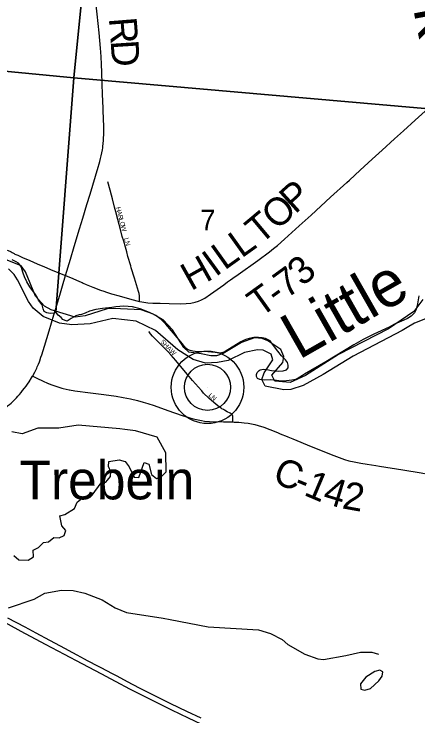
# Model space of a CAD drawing. Extents: x 1410790 to 1770854, y 448063 to 770588.
# Drawn here: x 1548544 to 1552911, y 621077 to 628670 of the extents above; entities that cross this region are included whole.
import ezdxf

# ---------------------------------------------------------------- set-up
doc = ezdxf.new("R2010")
doc.units = 0
for name, color, linetype in [('GM_X_County_Road', 7, 'Continuous'), ('GM_X_County_Road_Text', 7, 'Continuous'), ('GM_X_Major_River', 7, 'Continuous'), ('GM_X_Major_River_Text', 7, 'Continuous'), ('GM_X_Minor_Lake', 7, 'Continuous'), ('GM_X_Minor_River', 7, 'Continuous'), ('GM_X_Minor_River_Text', 7, 'Continuous'), ('GM_X_Section', 7, 'Continuous'), ('GM_X_Section_Text', 7, 'Continuous'), ('GM_X_Township_Road', 7, 'Continuous'), ('GM_X_Township_Road_Text', 7, 'Continuous'), ('GM_X_Township_Subdivision', 7, 'Continuous'), ('GM_X_Township_Subdivision_Text', 7, 'Continuous'), ('GM_X_Unincorporated', 7, 'Continuous'), ('GM_X_Unincorporated_Location', 7, 'Continuous'), ('GM_X_Unincorporated_Text', 7, 'Continuous'), ('GM_X_US_Route', 7, 'Continuous')]:
    doc.layers.add(name, color=color, linetype=linetype)

msp = doc.modelspace()

# ---------------------------------------------------------------- linework, layer by layer
at = {"layer": 'GM_X_County_Road'}
for points in [[(1549508.2, 627624), (1549507.3, 627650.8), (1549502.1, 627802.3), (1549497.6, 627911.9), (1549492.5, 628036.7), (1549488.6, 628126.5), (1549485.2, 628206.8), (1549482.1, 628256.7), (1549479.3, 628301.4), (1549464.4, 628464.7), (1549444, 628667), (1549425.8, 628836.6), (1549397.5, 629101.8), (1549381.4, 629253.7), (1549372.3, 629343.1), (1549344.5, 629616.5), (1549338.5, 629679.9), (1549335, 629723.3), (1549332.8, 629751.5), (1549330.7, 629782.3), (1549328.9, 629824.9), (1549327.6, 629859.6)], [(1549513, 627365.4), (1549514.1, 627400.6), (1549513.8, 627453), (1549508.2, 627624)], [(1549331.9, 626608.2), (1549366.8, 626722.6), (1549453.5, 627013.7), (1549463, 627048), (1549470.4, 627074.4), (1549478.7, 627106.6), (1549485.2, 627135.1), (1549492.5, 627168.6), (1549499.1, 627199.9), (1549503, 627222), (1549505.3, 627237.6), (1549508.5, 627269.9), (1549510.8, 627302.7), (1549511.9, 627328.7), (1549513, 627365.4)], [(1549100.3, 625839.9), (1549154.4, 626018.5), (1549194.8, 626154.3), (1549252.5, 626345.3), (1549287.7, 626463.3), (1549331.9, 626608.2)], [(1548470.7, 626114.6), (1548498.1, 626103.4), (1548511.1, 626097.4), (1548522.8, 626091.3), (1548536.7, 626083.1), (1548545.4, 626077.8), (1548553.6, 626073.5), (1548583.2, 626060), (1548636.1, 626037.5), (1548712.9, 626004.9), (1548795.4, 625969.3), (1548874.4, 625935), (1548963.3, 625896.8), (1549100.3, 625839.9)], [(1548745.6, 624754.3), (1548753.9, 624769), (1548768.1, 624795.2), (1548782.4, 624824), (1548789.8, 624839.1), (1548795.4, 624852.5), (1548808.4, 624883.4), (1548817.5, 624907.7), (1548824.9, 624927.9), (1548826.2, 624931.5), (1548835.3, 624958.9), (1548843.6, 624983.6), (1548873.1, 625078.7), (1548922.6, 625243.2), (1548975.1, 625416.3), (1548995.9, 625485.4), (1549045.4, 625655), (1549067.1, 625728), (1549100.3, 625839.9)], [(1548413.2, 624383.4), (1548450.8, 624412), (1548474.7, 624431.1), (1548493.3, 624447.1), (1548511.1, 624462.3), (1548526.3, 624475.8), (1548538.4, 624487.1), (1548551, 624499.7), (1548568.8, 624518.3), (1548585.7, 624537), (1548601.4, 624555.2), (1548619.2, 624575.6), (1548637, 624597.3), (1548656.1, 624621.7), (1548674.3, 624645.1), (1548689.5, 624666.8), (1548705.7, 624691.3), (1548734, 624735.3), (1548744.2, 624751.8), (1548745.6, 624754.3)], [(1548745.6, 624754.3), (1548795.8, 624729.1), (1548852.8, 624700.4), (1548912.7, 624673.1), (1548916.5, 624671.6)], [(1548916.5, 624671.6), (1548942.4, 624661.4), (1548973, 624650.2), (1549017.5, 624635.7), (1549060.8, 624623.7), (1549075.7, 624619.6), (1549107.6, 624611.4), (1549138.6, 624605)], [(1549138.6, 624605), (1549141.8, 624604.3), (1549201, 624593.9), (1549369.9, 624571.7), (1549513.3, 624554.2), (1549649.8, 624534.9), (1549724.3, 624522.5), (1549801.6, 624506.6), (1549878.3, 624488.2), (1549941.8, 624471.1), (1549989, 624456.7), (1550057.4, 624433.7), (1550206.5, 624382.7), (1550360.8, 624327.4), (1550432.4, 624304.3), (1550479.6, 624291.1), (1550533.6, 624278.6), (1550572.2, 624271.8), (1550604.4, 624267.4), (1550656.4, 624263.3), (1550807.7, 624258.5), (1550909.7, 624257.1)], [(1550909.7, 624257.1), (1550925.7, 624256.8), (1550974.6, 624254.6), (1551033.6, 624249.3), (1551076.1, 624243.7), (1551111.8, 624237.2), (1551147.2, 624229.2), (1551185.3, 624218.6), (1551244.9, 624199.4), (1551309.5, 624175.1), (1551391.9, 624142.6), (1551421.9, 624129.8), (1551496.8, 624100.4)], [(1551496.8, 624100.4), (1551503, 624098), (1551559.9, 624074.5), (1551755.9, 623993.3), (1552002, 623893.7), (1552060.1, 623871.3), (1552115.8, 623852.3), (1552162.7, 623838.5), (1552223, 623824.3), (1552294.1, 623812.9), (1552362.2, 623802.1), (1552456, 623786.2), (1552494.7, 623779.6), (1552747.4, 623739.8), (1552944.7, 623705.8), (1553096.5, 623679.4), (1553252.7, 623654.1)]]:
    msp.add_lwpolyline(points, dxfattribs=at)
at = {"layer": 'GM_X_Major_River'}
for points in [[(1552964.5, 625583.2), (1552867.5, 625453), (1552593.1, 625264.6), (1552050.4, 624985.8), (1551697.1, 624760.9), (1551529.2, 624684.4), (1551363.3, 624698), (1551330.8, 624764.8), (1551451.9, 624900.5), (1551459.3, 624966.4), (1551426.9, 625041.3), (1551288.9, 625136.4), (1551225.4, 625161.8), (1551143.4, 625165.6), (1551004.1, 625116.5), (1550805.3, 624998.6), (1550734.7, 624974.1), (1550670.6, 624971.4), (1550567, 624993.7), (1550435.2, 625012.6), (1550380.3, 625061.8), (1550256.3, 625252.9), (1550156.6, 625363.2), (1550041.9, 625427.8), (1549918.7, 625468.5), (1549694.7, 625481.4), (1549626.7, 625482.8), (1549550.5, 625480.5), (1549312.6, 625405.4), (1549204.2, 625391.8), (1548943.6, 625469.5), (1548874.4, 625509), (1548774.7, 625617.4), (1548666.4, 625882.2), (1548621.7, 625945.3), (1548435.2, 626023.4)], [(1551260.1, 624646.1), (1551223.6, 624715), (1551249.2, 624788.6), (1551342.4, 624928.9), (1551325.7, 624991.4), (1551236.6, 625035.4), (1551176.6, 625036.7), (1551035.8, 625009.7), (1550859.7, 624923.3), (1550745.1, 624899.7), (1550614.8, 624894.5), (1550481.5, 624933.4), (1550315.6, 625037.2), (1550074, 625246.8), (1549865.9, 625347.4), (1549610.3, 625377), (1549368.8, 625318.1), (1549170.3, 625308.3), (1549036.6, 625327.2), (1548860, 625399.2), (1548749.8, 625487.7), (1548699.3, 625558.9), (1548582.3, 625793.8), (1548545.5, 625850.7), (1548482.8, 625912.2)], [(1552993.9, 625372.2), (1552872.8, 625326.7), (1552793.6, 625278.3), (1552738.9, 625245.4), (1552212.2, 624968.2), (1551887.5, 624770.8), (1551670.7, 624651.3), (1551537.6, 624610.1), (1551459.4, 624603.8), (1551260.1, 624646.1)]]:
    msp.add_lwpolyline(points, dxfattribs=at)
at = {"layer": 'GM_X_Minor_Lake'}
for points in [[(1548542.8, 622813.3), (1548596.1, 622766.2), (1548698.2, 622760.5), (1548755, 622799.6), (1548752.2, 622869.9), (1548808.8, 622899), (1548861.9, 622952.3), (1548918.2, 622961.3), (1548975.1, 623006.5), (1549033.2, 623003.5), (1549085.8, 623030.7), (1549104.7, 623082.5), (1549061.4, 623133.4), (1549039.2, 623242.1), (1549093.6, 623255.2), (1549196.9, 623319.6), (1549228.2, 623389.3), (1549279.1, 623432.5), (1549387.9, 623466.8), (1549484.4, 623597.5), (1549536.6, 623606.6), (1549585.8, 623666), (1549588.7, 623718.1), (1549565.6, 623776.6), (1549570.5, 623828.7), (1549681.1, 623846.9), (1549744.9, 623829.7), (1549790.1, 623772.8), (1549842.3, 623659.6), (1549894.3, 623656.7), (1549949.2, 623818.2), (1550003.1, 623801.2), (1550031.2, 623690.4), (1550084.6, 623647.4), (1550135, 623662.5), (1550188.1, 623717.8), (1550185.6, 623924.4), (1550092.2, 624092.5), (1549858.9, 624162.7), (1549740.8, 624176.8), (1549686.8, 624181.7), (1549238.4, 624221.5), (1549029.4, 624191), (1548923.1, 624190.8), (1548800.8, 624188.9), (1548633.4, 624127.6), (1548521.5, 624149.6)], [(1552525.4, 621507.1), (1552530.4, 621553.2), (1552498.7, 621571.9), (1552444.3, 621559), (1552348.9, 621496.7), (1552289.3, 621423.7), (1552294.1, 621365.5), (1552338, 621354.5), (1552396.5, 621373.4)], [(1552396.5, 621373.4), (1552488.4, 621456.9), (1552525.4, 621507.1)]]:
    msp.add_lwpolyline(points, dxfattribs=at)
at = {"layer": 'GM_X_Minor_River'}
msp.add_lwpolyline([(1548482.9, 622246.6), (1548761.2, 622342.1), (1548878.6, 622404.3), (1549057.6, 622439.3), (1549183.8, 622433.2), (1549307.6, 622407), (1549496.8, 622333.5), (1549635.7, 622246.9), (1549759.1, 622196.6), (1550157, 622133.6), (1550233, 622120.2), (1550644.6, 622040.9), (1551187.3, 622009.5), (1551317, 621969.2), (1551444.2, 621904.8), (1551503.4, 621849.6), (1551688, 621744.1), (1551827.5, 621695.5), (1551891.5, 621688.4), (1552132.9, 621732.4), (1552291.8, 621767.8), (1552412.1, 621765.7), (1552483.9, 621746.4)], dxfattribs=at)
at = {"layer": 'GM_X_Section'}
for points in [[(1544399.7, 633789.9), (1549719.6, 633308.3), (1549189.3, 627980.4), (1543911.7, 628488)], [(1549719.6, 633308.3), (1555022.2, 632826.4), (1554631.8, 628627.9), (1554620.8, 627934.3), (1554618.6, 627918.3), (1554618, 627882.4), (1554617.3, 627836.4), (1554614.8, 627806.4), (1554624.4, 627780.3), (1554668.6, 627671.6), (1554687.9, 627625.3), (1554689.4, 627591.3), (1554684.9, 627563.4), (1554674.5, 627535.6), (1554652.2, 627519.9), (1554620, 627502.5), (1554585.9, 627497), (1554498, 627498.4), (1554418, 627499.6), (1554372, 627500.4), (1554330.2, 627507), (1554298.4, 627519.5), (1554266.6, 627536), (1549189.3, 627980.4)]]:
    msp.add_lwpolyline(points, close=True, dxfattribs=at)
for points in [[(1543911.7, 628488), (1549189.3, 627980.4), (1548997.2, 625446.3), (1548975, 625434.6), (1548940.9, 625431.2), (1548917, 625433.5), (1548897.1, 625437.9), (1548869.3, 625450.3), (1548859.7, 625480.4), (1548846.4, 625522.6), (1548807.3, 625575.2), (1548795.7, 625605.4), (1548774.3, 625637.7), (1548713.6, 625718.7), (1548680.5, 625773.2), (1548655.3, 625825.6), (1548641.9, 625865.8), (1548628.7, 625914), (1548625, 625932), (1548611.3, 625954.2), (1548591.7, 625974.5), (1548566, 625990.9), (1548522.2, 626009.6)], [(1552920.6, 625620), (1552905.3, 625534.3), (1552890.3, 625472.5), (1552873.8, 625438.8), (1552838.5, 625402.9), (1552796.8, 625376), (1552758.5, 625356.6), (1552655.9, 625314.3), (1552599.4, 625283.2), (1552434.2, 625205.8), (1552317.4, 625149.7), (1552216.5, 625093.3), (1551913.7, 624908.2), (1551685.6, 624773.8), (1551663.4, 624760.2), (1551617, 624730.9), (1551588.8, 624717.4), (1551548.6, 624708), (1551488.6, 624703), (1551436.6, 624699.8), (1551380.6, 624704.7), (1551312.8, 624711.8), (1551256.8, 624710.7), (1551200.9, 624717.6), (1551175.1, 624727.9), (1551165.4, 624750.1), (1551163.8, 624772.1), (1551174.1, 624792), (1551194.4, 624813.6), (1551206.5, 624819.4), (1551240.6, 624826.9), (1551276.6, 624824.3), (1551328.4, 624815.5), (1551402.3, 624808.3), (1551452.3, 624809.5), (1551490.4, 624820.9), (1551506.8, 624842.7), (1551509.3, 624872.6), (1551499.7, 624898.8), (1551480.2, 624931), (1551434.9, 624973.8), (1551397.7, 625022.3), (1551338.9, 625097.2), (1551313.5, 625133.6), (1551263.9, 625158.4), (1551226, 625169), (1551186.1, 625171.6), (1551136.1, 625170.4), (1551088, 625161.2), (1551049.8, 625147.8), (1551023.6, 625138.2), (1550995.4, 625124.7), (1550920.7, 625077.9), (1550856.1, 625036.9), (1550815.7, 625013.6), (1550787.6, 625006), (1550759.5, 625002.4), (1550719.6, 625007.1), (1550597.9, 625019), (1550525.9, 625016.2), (1550476, 625023), (1550448.1, 625029.4), (1550420.3, 625039.8), (1550400.5, 625056.1), (1550347.6, 625123), (1550269.1, 625216.2), (1550184.7, 625313.5), (1550133.5, 625366.3), (1550076.2, 625407.2), (1550008.8, 625442.2), (1549907.4, 625479.8), (1549823.8, 625501.1), (1549731.9, 625508.6), (1549643.9, 625504), (1549601.8, 625496.6), (1549499.6, 625486.3), (1549429.5, 625473.4), (1549361.2, 625456.5), (1549312.9, 625435.3), (1549272.6, 625419.9), (1549246.6, 625416.3), (1549210.4, 625404.9), (1549162, 625377.7), (1549117.6, 625348.4), (1549095.7, 625354.7), (1549071.9, 625367.1), (1549052.2, 625385.4), (1549022.7, 625413.9), (1548997.2, 625446.3), (1549189.3, 627980.4), (1554266.6, 627536)]]:
    msp.add_lwpolyline(points, dxfattribs=at)
at = {"layer": 'GM_X_Township_Road'}
for points in [[(1549901.8, 625560.8), (1549925.2, 625555.3), (1549967.4, 625548.6), (1549989.8, 625546.2), (1550043.5, 625543.7), (1550124.6, 625541.9), (1550220.8, 625538.9), (1550345.6, 625535.2), (1550404.9, 625537.9), (1550454.2, 625543.6), (1550502.7, 625553.9), (1550537.6, 625564.6), (1550571.4, 625578.6), (1550606.3, 625597.8), (1550666.6, 625638), (1550810.7, 625741.1), (1550853.6, 625771.3), (1550885.8, 625793.8), (1550909.7, 625811.1), (1550968.6, 625852.8), (1551179.1, 626004), (1551306.7, 626096.6), (1551350.7, 626131.9), (1551393.2, 626167.4), (1551468.3, 626235.8), (1551626.7, 626378.5), (1551755.2, 626495.6), (1551966.4, 626687.5), (1552141.4, 626846.1), (1552170.5, 626872.7), (1552286.4, 626979.3), (1552417.2, 627098.8), (1552522.7, 627197.2), (1552655.9, 627318.7), (1552754.2, 627405.4), (1552879.9, 627520.3), (1553092.2, 627713.3)], [(1549100.3, 625839.9), (1549178.9, 625809.7), (1549250.7, 625777.8), (1549280.5, 625764.3), (1549292.3, 625758.8), (1549325, 625743.9), (1549394.7, 625715.7), (1549480.2, 625682.4), (1549514.4, 625670.6), (1549542.6, 625661.6), (1549599.2, 625644.6), (1549681.2, 625621), (1549766.2, 625596.2), (1549832.6, 625577.9), (1549870.8, 625568.2), (1549901.8, 625560.8)]]:
    msp.add_lwpolyline(points, dxfattribs=at)
at = {"layer": 'GM_X_Township_Subdivision'}
for points in [[(1549901.8, 625560.8), (1549901.8, 625581.2), (1549901.8, 625604.1), (1549900, 625622.5), (1549895.9, 625645.9), (1549890.8, 625667.7), (1549868.5, 625740), (1549845.2, 625813), (1549811.4, 625925.1), (1549805.2, 625946.6), (1549775.9, 626046.9), (1549761.9, 626097.5), (1549747.7, 626148.1), (1549729.7, 626211.2), (1549714.8, 626265), (1549698.5, 626325.2), (1549666.3, 626445.7), (1549644, 626531.4), (1549630.5, 626582.1), (1549606.8, 626670.9), (1549596.1, 626712.2), (1549582.1, 626766.2), (1549559.6, 626854.5)], [(1550572.7, 624592.3), (1550569.4, 624595.8), (1550473, 624707.5), (1550436.7, 624749.8), (1550380.2, 624817.9), (1550292.1, 624923.8), (1550243.7, 624981.4), (1550208.1, 625019.5), (1550070.1, 625155), (1550040.5, 625186), (1550019.1, 625211.3), (1550005.9, 625230.6), (1550002.5, 625236.5)], [(1550909.7, 624257.1), (1550909.7, 624286.7), (1550909.7, 624313.2), (1550909.2, 624321.5), (1550907.1, 624329.7), (1550901.4, 624337.1), (1550892.7, 624344.1), (1550880.9, 624351.4), (1550849.2, 624367.8), (1550820.1, 624383.5), (1550808.9, 624390.3), (1550791.4, 624400.4), (1550786.3, 624404.3), (1550775.2, 624411.5), (1550748.3, 624431), (1550705.1, 624466.6), (1550651.1, 624514.8), (1550594.1, 624569.3), (1550572.7, 624592.3)]]:
    msp.add_lwpolyline(points, dxfattribs=at)
at = {"layer": 'GM_X_Unincorporated'}
for radius in [392.8, 249]:
    msp.add_circle((1550635.9, 624632), radius, dxfattribs=at)
at = {"layer": 'GM_X_Unincorporated_Location'}
msp.add_line((1550635.9, 624632), (1550635.9, 624632), dxfattribs=at)
at = {"layer": 'GM_X_US_Route'}
for points in [[(1547431, 622630.3), (1547588.3, 622547.5), (1548007.4, 622322.4), (1548169.4, 622235.8), (1548372.4, 622128.3), (1548617.9, 621995.9), (1548881.2, 621855.2), (1549086.8, 621745.6), (1549278, 621644), (1549489.6, 621532), (1549582.2, 621482.5), (1549643.1, 621450.4), (1549790.8, 621372.1), (1549930.8, 621300.4), (1550095, 621218.2), (1550248.1, 621143.2), (1550425.8, 621058.5), (1550561.9, 620993.4), (1550677.3, 620938.4), (1551055.1, 620763), (1551139.9, 620722.5)], [(1548473.8, 622139.8), (1548662.2, 622039.9), (1548777.8, 621978), (1548928.2, 621897.4), (1549041, 621837.2), (1549222.7, 621738.7), (1549303.4, 621694.9), (1549335.3, 621677.9), (1549454, 621614.8), (1549483.1, 621599.6), (1549605, 621535.5), (1549654.5, 621510), (1549767.7, 621450.4), (1549898.5, 621382.1), (1550003.6, 621328.3), (1550135.2, 621261.5), (1550235.4, 621212.5), (1550409.6, 621128.4), (1550563.7, 621055.2)]]:
    msp.add_lwpolyline(points, dxfattribs=at)

# ---------------------------------------------------------------- texts
at = {"layer": 'GM_X_County_Road_Text'}
for s, rotation, p in [('R', 274.59478, (1549568.2, 628624.7)), ('D', 273.73291, (1549587.9, 628380.3)), ('C', 337.56297, (1551324.9, 623611.8)), ('1', 337.04468, (1551665.8, 623470.9)), ('-', 337.52306, (1551552.6, 623517.8)), ('4', 343.09129, (1551868.5, 623387.1)), ('2', 349.65719, (1552081.8, 623324.5))]:
    msp.add_text(s, height=300, rotation=rotation, dxfattribs=at).set_placement(p)
at = {"layer": 'GM_X_Major_River_Text'}
msp.add_text('Little', height=499.99, rotation=29.64798, dxfattribs=at).set_placement((1551622.5, 624924.7))
at = {"layer": 'GM_X_Minor_River_Text'}
msp.add_text('Creek', height=499.9, rotation=281.10658, dxfattribs=at).set_placement((1552581.5, 630143.1))
at = {"layer": 'GM_X_Section_Text'}
msp.add_text('7', height=221, rotation=0.00001, dxfattribs=at).set_placement((1550558, 626331.8))
at = {"layer": 'GM_X_Township_Road_Text'}
for s, rotation, p in [('P', 42.13977, (1551583, 626498.7)), ('O', 42.16723, (1551387.4, 626321.5)), ('T', 39.98149, (1551206, 626169.2)), ('L', 35.52312, (1551003.2, 626023.2)), ('L', 35.45896, (1550820.1, 625892.8)), ('I', 36.09649, (1550721.3, 625820.7)), ('H', 29.26052, (1550458.1, 625670.6)), ('3', 41.95106, (1551665.9, 625715.7)), ('7', 36.09293, (1551490.6, 625585.8)), ('T', 35.66123, (1551206.2, 625381.6)), ('-', 35.71276, (1551388.8, 625512.5))]:
    msp.add_text(s, height=300, rotation=rotation, dxfattribs=at).set_placement(p)
at = {"layer": 'GM_X_Township_Subdivision_Text'}
for s, rotation, p in [('H', 283.59096, (1549645.4, 626577.4)), ('A', 283.59096, (1549655.7, 626534.6)), ('R', 283.95295, (1549666.1, 626491.5)), ('L', 285.59998, (1549676.1, 626451.5)), ('O', 286.15568, (1549685.7, 626417.1)), ('W', 286.1865, (1549697.9, 626374.8)), ('LN', 284.74866, (1549733.3, 626243.2)), ('SHAW', 314.02672, (1550122.7, 625120.8)), ('L', 317.164, (1550642, 624539.9)), ('N', 319.86047, (1550669.7, 624514.3))]:
    msp.add_text(s, height=50, rotation=rotation, dxfattribs=at).set_placement(p)
at = {"layer": 'GM_X_Unincorporated_Text'}
msp.add_text('Trebein', height=417, rotation=0.00001, dxfattribs=at).set_placement((1548602.2, 623420.1))

doc.saveas('drawing.dxf')
